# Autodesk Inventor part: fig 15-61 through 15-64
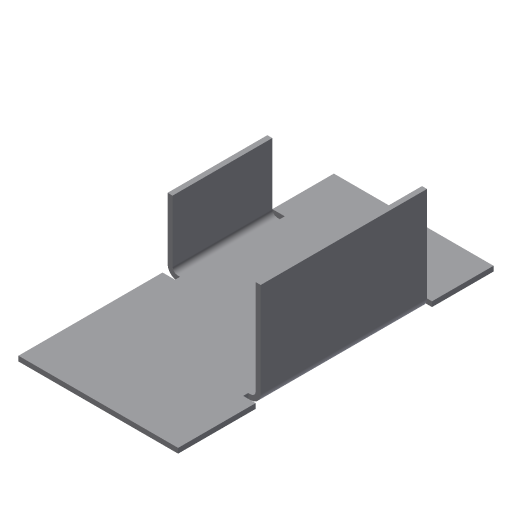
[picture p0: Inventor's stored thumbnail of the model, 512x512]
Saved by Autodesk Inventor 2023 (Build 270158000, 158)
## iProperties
Created: 2002-04
Part Number: fig 15-61 through 15-64
Document SubType Name: Sheet Metal
Density: 1 g/cm^3
Sheet Metal Rule: Default
Material: Generic
Appearance: Default
Control State: 0
Master: False
Checked Out: False
Shininess: 77.0
Angle Display Precision: 2
Document Length Units: 11269
Document Angle Units: 11279
Document Time Units: 11290
Document Mass Units: 11283
Document Length Units Precision: 3
Document Angle Units Precision: 2
Compacted: True
Density: 0.0
Volumn: 0.0
Area: 0.0
PropertySet Name: Model Information
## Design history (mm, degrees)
node "Face1"
  sketch "Sketch1"
    geometry: L1 (-33.176, 5.765)-(14.235, 5.765); L2 (14.235, 5.765)-(14.235, -18.235); L3 (14.235, -18.235)-(-33.176, -18.235); L4 (-33.176, -18.235)-(-33.176, 5.765)
    constraints: 8 end point, 2 parallel, 1 horizontal, 1 perpendicular
node "Flange1"
node "Flange2"
body "Solid1"
face "Plate1" dims "d24" = 0.75 (= Thickness)
sketch "Sketch2"
  geometry: L1 (37.412, 0)-(22.412, 0); L2 (22.412, 0)-(22.412, 10); L3 (22.412, 10)-(37.412, 10); L4 (37.412, 10)-(37.412, 0)
  constraints: 8 end point
face "Plate2" dims "d1" = 10, "d2" = 15, "d4" = 10, "d5" = 90 deg, "d6" = 0.75 (= BendRadius), "d24" = 0.75 (= Thickness), "MinimumRemnant" = 1.5 (= 2 x Thickness), "BendReliefWidth" = 0.75 (= Thickness)
bend "Bend1" dims "d3" = 0.75 (= BendRadius), "d4" = 10, "d5" = 90 deg, "d6" = 0.75 (= BendRadius), "d15" = 0.75 (= BendReliefWidth), "d16" = 0.375 (= BendReliefDepth), "d17" = 1.5 (= MinimumRemnant), "d24" = 0.75 (= Thickness), "SeamGap" = 0.01, "MinimumRemnant" = 1.5 (= 2 x Thickness), "BendReliefWidth" = 0.75 (= Thickness)
sketch "Sketch3"
  geometry: L1 (10, 0)-(35, 0); L2 (35, 0)-(35, 15); L3 (35, 15)-(10, 15); L4 (10, 15)-(10, 0)
  constraints: 8 end point
face "Plate3" dims "d7" = 10, "d8" = 25, "d10" = 15, "d11" = 90 deg, "d12" = 0.75 (= BendRadius), "d24" = 0.75 (= Thickness), "MinimumRemnant" = 1.5 (= 2 x Thickness), "BendReliefWidth" = 0.75 (= Thickness)
bend "Bend2" dims "d9" = 0.75 (= BendRadius), "d10" = 15, "d11" = 90 deg, "d12" = 0.75 (= BendRadius), "d18" = 0.75 (= BendReliefWidth), "d19" = 0.375 (= BendReliefDepth), "d20" = 1.5 (= MinimumRemnant), "d24" = 0.75 (= Thickness), "SeamGap" = 0.01, "MinimumRemnant" = 1.5 (= 2 x Thickness), "BendReliefWidth" = 0.75 (= Thickness)
other parameters: "Thickness" = 0.75, "BendRadius" = 0.75 (= Thickness), "BendReliefDepth" = 0.375 (= 0.5 x Thickness), "CornerReliefSize" = 3 (= 4 x Thickness), "TransitionRadius" = 0.75 (= BendRadius), "d0" = 0.75 (= BendRadius), "d13" = 0.75 (= BendRadius), "JacobiRadiusSize" = 0.75 (= Thickness), "GapSize" = 0.75 (= Thickness)
